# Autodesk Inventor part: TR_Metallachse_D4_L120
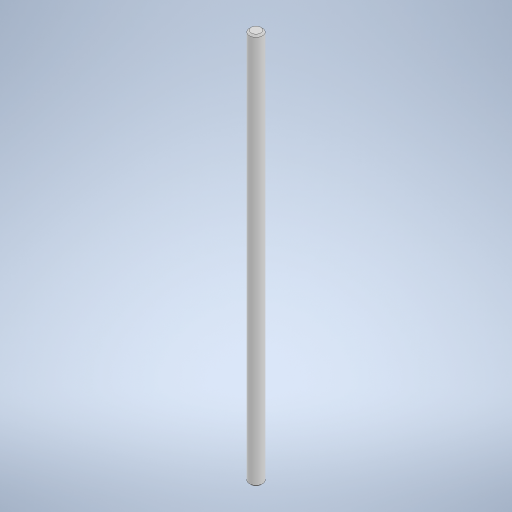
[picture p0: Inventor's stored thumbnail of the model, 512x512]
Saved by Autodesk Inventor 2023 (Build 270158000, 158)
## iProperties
Created: 2023-11
Part Number: TR_Metallachse_D4_L120
Material: Generisch
Document SubType Name: Modeling
Designer: Greiner
Density: 1 g/cm^3
Appearance: Vorgabe
Author: Greiner
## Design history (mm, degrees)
sketch "Skizze1"
  geometry: C1 r 2 at (0, 0); 1 further point
  constraints: 1 centre point, 1 coincident
  dimensions: "d0" = 4 diameter of C1 (= AchsDurchmesser)
extrude "Extrusion1" new body sketch "Skizze1" distance "d1" = 120; taper "d2" = 0 deg
chamfer "Fase1" distance "d3" = 0.5 (= AchsFase); stored, may be unused: second distance "d4" = 2, angle "d5" = 45 deg
node "Volumenkörper1"
other parameters: "Radius" = 2.075 [user parameter], "Fasen" = 0.5 [user parameter], "Dicke" = 0.8 [user parameter], "Breitloch" = 2 [user parameter], "Langloch" = 32 [user parameter], "AchteckUmkreis" = 6 [user parameter], "DAchsAufnahme" = 4.1 [user parameter], "AchsDurchmesser" = 4 [user parameter; used in 1 equation term], "AchsFase" = 0.5 [user parameter; used in 1 equation term]
